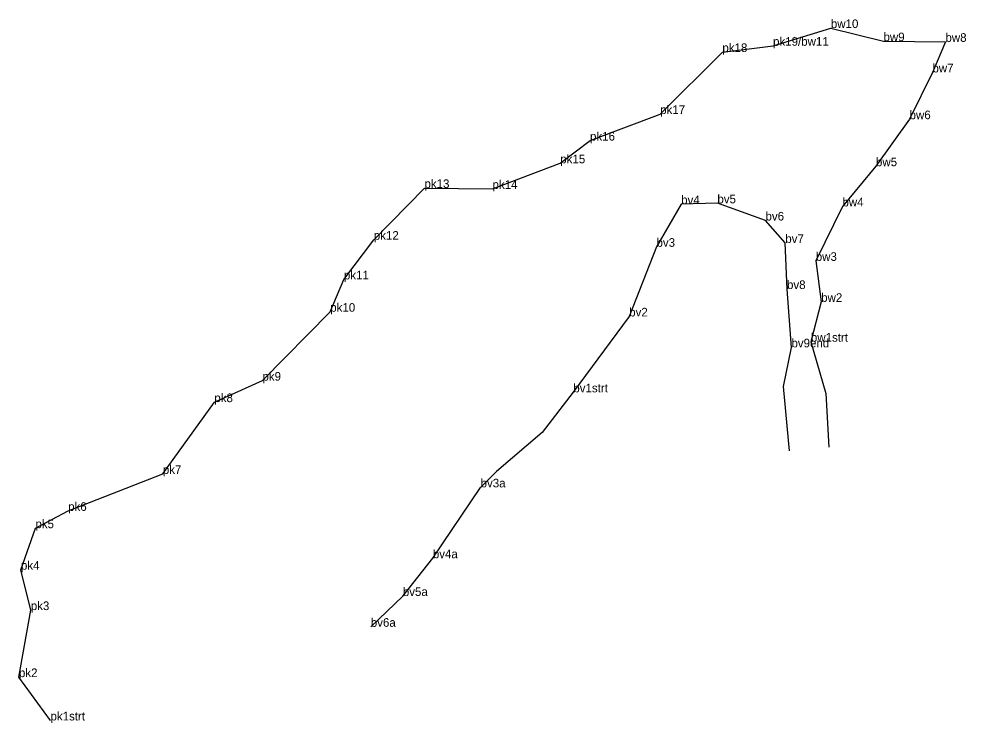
# Model space of a CAD drawing. Extents: x 2072529 to 2267990, y 436423 to 470008.
# Drawn here: x 2236884 to 2237544, y 437920 to 438410 of the extents above; entities that cross this region are included whole.
import ezdxf

# ---------------------------------------------------------------- set-up
doc = ezdxf.new("R2010")
doc.units = 0
doc.layers.add('Level 3', color=7, linetype='Continuous')
doc.layers.add('Old_Level_52', color=7, linetype='Continuous')

msp = doc.modelspace()

# ---------------------------------------------------------------- linework, layer by layer
at = {"layer": 'Level 3'}
for p, q in [((2237449.833, 438404.177), (2237449.833, 438404.177)), ((2237409.563, 438391.836), (2237409.563, 438391.836)), ((2237486.488, 438394.985), (2237486.488, 438394.985)), ((2237529.642, 438394.565), (2237529.642, 438394.565)), ((2237374.281, 438387.481), (2237374.281, 438387.481)), ((2237520.576, 438373.276), (2237520.576, 438373.276)), ((2237330.938, 438344.335), (2237330.938, 438344.335)), ((2237504.684, 438340.716), (2237504.684, 438340.716)), ((2237282.095, 438325.825), (2237282.095, 438325.825)), ((2237261.362, 438310.023), (2237261.362, 438310.023)), ((2237481.263, 438308.001), (2237481.263, 438308.001)), ((2237166.771, 438292.821), (2237166.771, 438292.821)), ((2237214.218, 438292.243), (2237214.218, 438292.243)), ((2237345.582, 438281.579), (2237345.582, 438281.579)), ((2237370.804, 438282.167), (2237370.804, 438282.167)), ((2237457.911, 438280.025), (2237457.911, 438280.025)), ((2237404.322, 438270.184), (2237404.322, 438270.184)), ((2237131.475, 438256.806), (2237131.475, 438256.806)), ((2237328.397, 438251.907), (2237328.397, 438251.907)), ((2237418.112, 438254.561), (2237418.112, 438254.561)), ((2237439.314, 438242.094), (2237439.314, 438242.094)), ((2237110.683, 438229.193), (2237110.683, 438229.193)), ((2237419.3, 438222.512), (2237419.3, 438222.512)), ((2237443.079, 438213.567), (2237443.079, 438213.567)), ((2237101.148, 438206.694), (2237101.148, 438206.694)), ((2237309.376, 438203.417), (2237309.376, 438203.417)), ((2237435.929, 438185.838), (2237435.929, 438185.838)), ((2237422.375, 438181.891), (2237422.375, 438181.891)), ((2237053.914, 438158.728), (2237053.914, 438158.728)), ((2237270.46, 438150.615), (2237270.46, 438150.615)), ((2237020.419, 438143.773), (2237020.419, 438143.773)), ((2236984.528, 438093.845), (2236984.528, 438093.845)), ((2237205.881, 438084.44), (2237205.881, 438084.44)), ((2236918.587, 438068.083), (2236918.587, 438068.083)), ((2236895.789, 438056.043), (2236895.789, 438056.043)), ((2237172.594, 438035.113), (2237172.594, 438035.113)), ((2236885.733, 438027.144), (2236885.733, 438027.144)), ((2237151.698, 438008.829), (2237151.698, 438008.829)), ((2236892.561, 437999.041), (2236892.561, 437999.041)), ((2237129.393, 437987.403), (2237129.393, 437987.403)), ((2236884.323, 437952.374), (2236884.323, 437952.374)), ((2236906.285, 437922.218), (2236906.285, 437922.218))]:
    msp.add_line(p, q, dxfattribs=at)
at = {"layer": 'Old_Level_52'}
for points in [[(2236906.285, 437922.218), (2236884.323, 437952.374), (2236892.561, 437999.041), (2236885.733, 438027.144), (2236895.789, 438056.043), (2236918.587, 438068.083), (2236984.528, 438093.845), (2237020.419, 438143.773), (2237053.914, 438158.728), (2237101.148, 438206.694), (2237110.683, 438229.193), (2237131.475, 438256.806), (2237166.771, 438292.821), (2237214.218, 438292.243), (2237261.362, 438310.023), (2237282.095, 438325.825), (2237330.938, 438344.335), (2237374.281, 438387.481), (2237409.563, 438391.836), (2237449.833, 438404.177), (2237486.488, 438394.985), (2237529.642, 438394.565), (2237520.576, 438373.276), (2237504.684, 438340.716), (2237481.263, 438308.001), (2237457.911, 438280.025), (2237439.314, 438242.094), (2237443.079, 438213.567), (2237435.929, 438185.838), (2237446.36, 438149.849), (2237448.363, 438112.408)], [(2237421.034, 438109.873), (2237416.868, 438154.614), (2237422.375, 438181.891), (2237419.3, 438222.512), (2237418.112, 438254.561), (2237404.322, 438270.184), (2237370.804, 438282.167), (2237345.582, 438281.579), (2237328.397, 438251.907), (2237309.376, 438203.417), (2237270.46, 438150.615), (2237248.854, 438122.615), (2237217.016, 438095.445)], [(2237129.393, 437987.403), (2237151.698, 438008.829), (2237172.594, 438035.113), (2237205.881, 438084.44), (2237217.016, 438095.445)]]:
    msp.add_lwpolyline(points, dxfattribs=at)

# ---------------------------------------------------------------- texts
for s, p in [('bw10', (2237449.833, 438404.177)), ('pk19/bw11', (2237409.563, 438391.836)), ('bw9', (2237486.488, 438394.985)), ('bw8', (2237529.642, 438394.565)), ('pk18', (2237374.281, 438387.481)), ('bw7', (2237520.576, 438373.276)), ('pk17', (2237330.938, 438344.335)), ('bw6', (2237504.684, 438340.716)), ('pk16', (2237282.095, 438325.825)), ('pk15', (2237261.362, 438310.023)), ('bw5', (2237481.263, 438308.001)), ('pk13', (2237166.771, 438292.821)), ('pk14', (2237214.218, 438292.243)), ('bv4', (2237345.582, 438281.579)), ('bv5', (2237370.804, 438282.167)), ('bw4', (2237457.911, 438280.025)), ('bv6', (2237404.322, 438270.184)), ('pk12', (2237131.475, 438256.806)), ('bv3', (2237328.397, 438251.907)), ('bv7', (2237418.112, 438254.561)), ('bw3', (2237439.314, 438242.094)), ('pk11', (2237110.683, 438229.193)), ('bv8', (2237419.3, 438222.512)), ('bw2', (2237443.079, 438213.567)), ('pk10', (2237101.148, 438206.694)), ('bv2', (2237309.376, 438203.417)), ('bw1strt', (2237435.929, 438185.838)), ('bv9end', (2237422.375, 438181.891)), ('pk9', (2237053.914, 438158.728)), ('bv1strt', (2237270.46, 438150.615)), ('pk8', (2237020.419, 438143.773)), ('pk7', (2236984.528, 438093.845)), ('bv3a', (2237205.881, 438084.44)), ('pk6', (2236918.587, 438068.083)), ('pk5', (2236895.789, 438056.043)), ('bv4a', (2237172.594, 438035.113)), ('pk4', (2236885.733, 438027.144)), ('bv5a', (2237151.698, 438008.829)), ('pk3', (2236892.561, 437999.041)), ('bv6a', (2237129.393, 437987.403)), ('pk2', (2236884.323, 437952.374)), ('pk1strt', (2236906.285, 437922.218))]:
    msp.add_text(s, height=6).set_placement(p)

doc.saveas('drawing.dxf')
